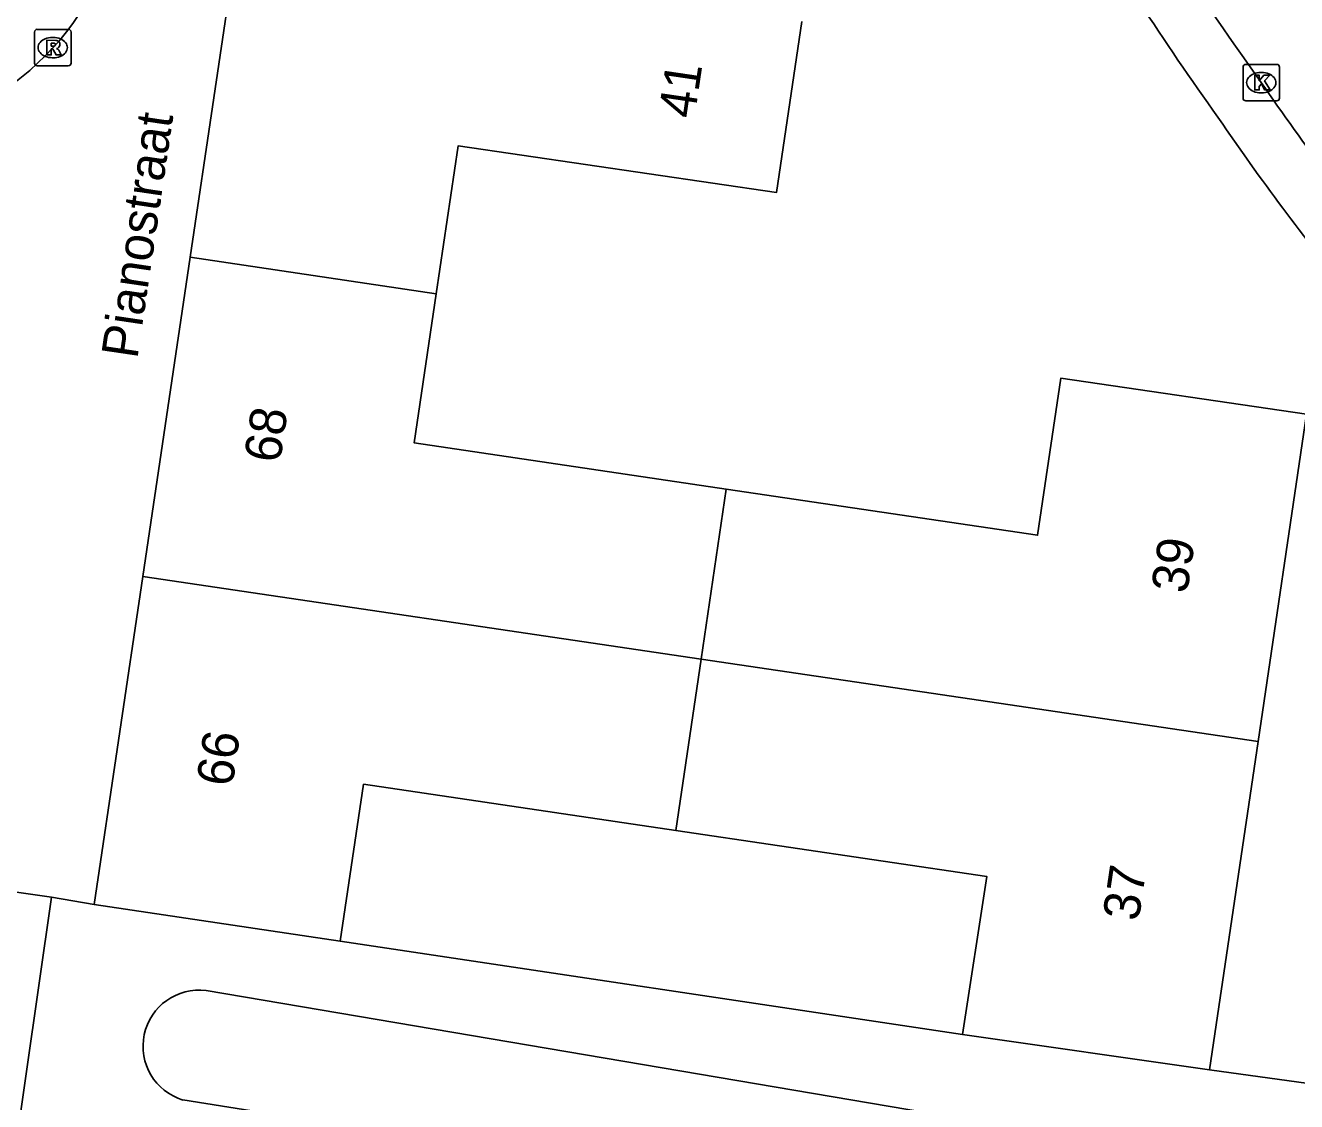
# Model space of a CAD drawing. Extents: x 164150 to 165261, y 382513 to 383432.
# Drawn here: x 164531.78 to 164566.64, y 383245.45 to 383274.96 of the extents above; entities that cross this region are included whole.
import ezdxf

# ---------------------------------------------------------------- set-up
doc = ezdxf.new("R2010")
doc.units = 0
for name, color, linetype in [('IMGEO_Greppel_droge_sloot', 7, 'Continuous'), ('IMGEO_Groenvoorziening', 7, 'Continuous'), ('IMGEO_Kolk', 7, 'Continuous'), ('IMGEO_Muur', 7, 'Continuous'), ('IMGEO_Openbare_ruimte_label', 7, 'Continuous'), ('IMGEO_Pand', 7, 'Continuous'), ('IMGEO_Pand_nummerreeks', 7, 'Continuous'), ('IMGEO_Rijbaan_lokaal_open', 7, 'Continuous'), ('IMGEO_Rioolput', 7, 'Continuous'), ('IMGEO_Voetpad_gesloten', 7, 'Continuous'), ('IMGEO_Voetpad_open', 7, 'Continuous')]:
    doc.layers.add(name, color=color, linetype=linetype)

msp = doc.modelspace()

# ---------------------------------------------------------------- linework, layer by layer
at = {"layer": 'IMGEO_Greppel_droge_sloot'}
msp.add_lwpolyline([(164536.099, 383245.494), (164577.946, 383238.829), (164578.341, 383241.442), (164536.737, 383248.494)], dxfattribs=at)
msp.add_arc((164536.543, 383246.967), 1.539, 82.7497, 253.2382, dxfattribs=at)
at = {"layer": 'IMGEO_Groenvoorziening'}
for points in [[(164540.41, 383249.845), (164557.474, 383247.292)], [(164564.251, 383246.318), (164583.934, 383243.607)]]:
    msp.add_lwpolyline(points, dxfattribs=at)
at = {"layer": 'IMGEO_Kolk'}
for p, q in [((164565.169, 383272.966), (164565.169, 383273.818)), ((164565.244, 383273.892), (164566.096, 383273.892)), ((164565.657, 383273.672), (164565.682, 383273.672)), ((164566.17, 383273.818), (164566.17, 383272.966)), ((164566.096, 383272.892), (164565.244, 383272.892)), ((164565.68, 383273.112), (164565.655, 383273.112))]:
    msp.add_line(p, q, dxfattribs=at)
for points in [[(164565.169, 383272.966), (164565.169, 383273.818)], [(164565.244, 383273.892), (164566.096, 383273.892)], [(164565.49, 383273.592), (164565.613, 383273.592), (164565.613, 383273.441), (164565.743, 383273.592), (164565.907, 383273.592), (164565.761, 383273.441), (164565.914, 383273.192), (164565.762, 383273.192), (164565.677, 383273.356), (164565.613, 383273.289), (164565.613, 383273.192), (164565.49, 383273.192), (164565.49, 383273.592)], [(164566.17, 383273.818), (164566.17, 383272.966)], [(164566.096, 383272.892), (164565.244, 383272.892)]]:
    msp.add_lwpolyline(points, dxfattribs=at)
for centre, start, end in [((164565.246, 383273.816), 91.552, 178.448), ((164565.246, 383273.816), 91.552, 178.448), ((164566.094, 383273.816), 1.552, 88.448), ((164566.094, 383273.816), 1.552, 88.448), ((164565.246, 383272.968), 181.552, 268.448), ((164565.246, 383272.968), 181.552, 268.448), ((164566.094, 383272.968), 271.552, 358.448), ((164566.094, 383272.968), 271.552, 358.448)]:
    msp.add_arc(centre, 0.0765, start, end, dxfattribs=at)
for centre, major_axis, ratio, start_param, end_param in [((164565.656, 383273.392), (-0.387, 0.002), 0.722429, 4.712389, 7.853982), ((164565.681, 383273.392), (-0.39, 0.002), 0.717154, 1.570796, 4.712389)]:
    msp.add_ellipse(centre, major_axis=major_axis, ratio=ratio, start_param=start_param, end_param=end_param, dxfattribs=at)
at = {"layer": 'IMGEO_Muur'}
msp.add_lwpolyline([(164557.474, 383247.292), (164540.41, 383249.845)], dxfattribs=at)
at = {"layer": 'IMGEO_Pand'}
for points in [[(164536.299, 383268.602), (164537.597, 383277.356)], [(164553.067, 383275.067), (164552.375, 383270.375), (164543.647, 383271.663), (164543.047, 383267.603)], [(164534.999, 383259.847), (164536.299, 383268.602)], [(164536.299, 383268.602), (164543.047, 383267.603)], [(164543.047, 383267.603), (164542.443, 383263.513), (164550.997, 383262.244)], [(164550.997, 383262.244), (164559.534, 383260.978), (164560.177, 383265.291), (164566.914, 383264.296), (164565.584, 383255.322)], [(164550.307, 383257.582), (164550.997, 383262.244)], [(164533.666, 383250.858), (164534.999, 383259.847)], [(164534.999, 383259.847), (164550.307, 383257.582)], [(164550.307, 383257.582), (164549.612, 383252.884)], [(164565.584, 383255.322), (164550.307, 383257.582)], [(164565.584, 383255.322), (164564.251, 383246.318)], [(164549.612, 383252.884), (164541.054, 383254.153), (164540.41, 383249.845)], [(164557.474, 383247.292), (164558.145, 383251.619), (164549.612, 383252.884)], [(164533.666, 383250.858), (164540.41, 383249.845)], [(164557.474, 383247.292), (164564.251, 383246.318)]]:
    msp.add_lwpolyline(points, dxfattribs=at)
at = {"layer": 'IMGEO_Rijbaan_lokaal_open'}
for centre, radius, start, end in [((164693.124, 383364.005), 156.382, 208.2557, 215.41089), ((164526.923, 383279.475), 7.601, 279.49, 351.057), ((164626.306, 383315.026), 73.553, 214.4746, 219.3674)]:
    msp.add_arc(centre, radius, start, end, dxfattribs=at)
at = {"layer": 'IMGEO_Rioolput'}
for p, q in [((164532.028, 383273.927), (164532.028, 383274.779)), ((164532.103, 383274.853), (164532.955, 383274.853)), ((164533.029, 383274.779), (164533.029, 383273.927)), ((164532.516, 383274.633), (164532.541, 383274.633)), ((164532.539, 383274.073), (164532.514, 383274.073)), ((164532.955, 383273.853), (164532.103, 383273.853))]:
    msp.add_line(p, q, dxfattribs=at)
for points in [[(164532.028, 383273.927), (164532.028, 383274.779)], [(164532.103, 383274.853), (164532.955, 383274.853)], [(164533.029, 383274.779), (164533.029, 383273.927)], [(164532.617, 383274.551), (164532.365, 383274.553), (164532.365, 383274.153)], [(164532.365, 383274.153), (164532.489, 383274.153), (164532.489, 383274.315), (164532.5, 383274.315)], [(164532.543, 383274.472), (164532.489, 383274.472), (164532.489, 383274.391)], [(164532.489, 383274.391), (164532.541, 383274.391)], [(164532.547, 383274.286), (164532.618, 383274.153), (164532.758, 383274.153), (164532.693, 383274.279)], [(164532.955, 383273.853), (164532.103, 383273.853)]]:
    msp.add_lwpolyline(points, dxfattribs=at)
for centre, radius, start, end in [((164532.105, 383274.777), 0.0765, 91.552, 178.448), ((164532.105, 383274.777), 0.0765, 91.552, 178.448), ((164532.953, 383274.777), 0.0765, 1.552, 88.448), ((164532.953, 383274.777), 0.0765, 1.552, 88.448), ((164532.499, 383274.262), 0.0533, 26.0293, 88.6989), ((164532.525, 383274.58), 0.19, 274.7715, 282.9687), ((164532.549, 383274.376), 0.0964, 77.0061, 93.1865), ((164532.563, 383274.433), 0.0378, 276.6634, 79.6772), ((164532.616, 383274.441), 0.109, 350.3612, 89.416), ((164532.614, 383274.441), 0.112, 277.5842, 350.9817), ((164532.598, 383274.226), 0.108, 29.5134, 73.7905), ((164532.105, 383273.929), 0.0765, 181.552, 268.448), ((164532.105, 383273.929), 0.0765, 181.552, 268.448), ((164532.953, 383273.929), 0.0765, 271.552, 358.448), ((164532.953, 383273.929), 0.0765, 271.552, 358.448)]:
    msp.add_arc(centre, radius, start, end, dxfattribs=at)
for centre, major_axis, ratio, start_param, end_param in [((164532.515, 383274.353), (-0.387, 0.002), 0.722429, 4.712389, 7.853982), ((164532.54, 383274.353), (-0.39, 0.002), 0.717154, 1.570796, 4.712389)]:
    msp.add_ellipse(centre, major_axis=major_axis, ratio=ratio, start_param=start_param, end_param=end_param, dxfattribs=at)
at = {"layer": 'IMGEO_Voetpad_gesloten'}
for points in [[(164530.556, 383251.332), (164532.495, 383251.052)], [(164530.74, 383238.876), (164532.495, 383251.052)]]:
    msp.add_lwpolyline(points, dxfattribs=at)
at = {"layer": 'IMGEO_Voetpad_open'}
msp.add_lwpolyline([(164532.495, 383251.052), (164533.666, 383250.858)], dxfattribs=at)
for centre, radius, start, end in [((164640.067, 383326.157), 92.732, 213.18571, 215.54367), ((164621.712, 383311.398), 69.23, 214.43557, 219.42218)]:
    msp.add_arc(centre, radius, start, end, dxfattribs=at)

# ---------------------------------------------------------------- texts
at = {"layer": 'IMGEO_Openbare_ruimte_label'}
msp.add_text('Pianostraat', height=1, rotation=81.6024, dxfattribs=at).set_placement((164534.846, 383265.795))
at = {"layer": 'IMGEO_Pand_nummerreeks'}
for s, rotation, p in [('41', 81.6006, (164550.124, 383272.384)), ('68', 81.6236, (164538.759, 383262.938)), ('39', 81.572, (164563.635, 383259.36)), ('66', 81.6236, (164537.452, 383254.061)), ('37', 81.572, (164562.304, 383250.374))]:
    msp.add_text(s, height=1, rotation=rotation, dxfattribs=at).set_placement(p)

doc.saveas('drawing.dxf')
